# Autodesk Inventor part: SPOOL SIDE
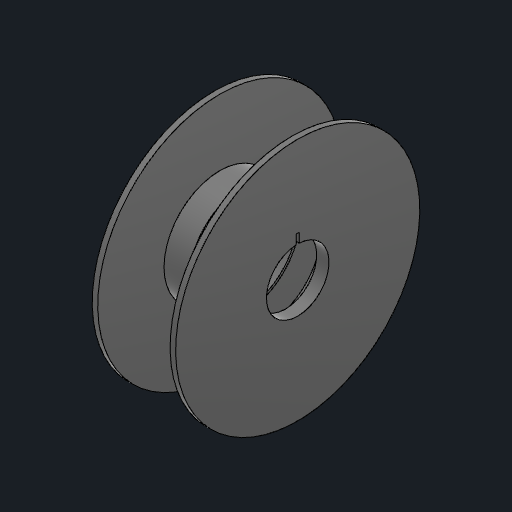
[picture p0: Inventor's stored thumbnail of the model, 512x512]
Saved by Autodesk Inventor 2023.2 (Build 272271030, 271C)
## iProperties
Created: 2022-11
Part Number: SPOOL SIDE
Material: Generic
Document SubType Name: Modeling
Designer: AR
Mass: 287.917 g
Surface Area: 1494.22 cm^2
Volume: 287.917 cm^3
Density: 1 g/cm^3
Appearance: Smooth - Black
Author: AR
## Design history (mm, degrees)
derived "_2 SPOOL CORD WRAP MP.ipt"
feature "PRUSA SPOOL SIDE::_2 SPOOL CORD WRAP MP.ipt" dims "d0" = 10
tag "TaggingFeature1"
node "PRUSA SPOOL SIDE"
